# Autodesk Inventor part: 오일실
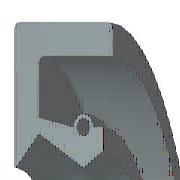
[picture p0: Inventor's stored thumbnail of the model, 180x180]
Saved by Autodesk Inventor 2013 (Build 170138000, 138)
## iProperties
IsCustomPart: 0
Created: 2014-10
Part Number: 오일실
Material: 고무
Description: 오일-실
Document SubType Name: Modeling
Standard: KS B 2804
Designer: KYOUNG IL JANG
Standards Organization: KS
Language: ko-KR
Size Designation: D - 17 32 8
Categories: <MemberInstance><Categories><Category DisplayName="샤프트 부품" InternalName="7f7aeb1f-a693-4053-b835-cee3144e0d98" Mnemonic="SHFT"><Category DisplayName="실링" Intern
Density: 0.93 g/cm^3
Mass: 2.28027 g
Surface Area: 32.1224 cm^2
Volume: 2.45191 cm^3
Author: SeoGD™ [www.esajin.kr]
Revision Number: 1
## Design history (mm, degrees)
revolve "본체" stored, may be unused: angle "d17" = 90 deg
revolve "스프링1" stored, may be unused: angle "d18" = 90 deg
body "Solid1"
sketch "스케치1"
  geometry: L1 (0, 16)-(8, 16); L2 (8, 14.25)-(1.75, 14.25); L3 (1.75, 10.25)-(4.9, 8.5); L4 (4.9, 8.5)-(0, 8.5); L5 (0, 0)-(9.586, 0) reference; L6 (4.9, 8.5)-(6.3, 9.375); L7 (0, 18)-(0, -3) reference; L8 (-1.941, 0)-(11.507, 0) reference; L9 (4.2, 10.6)-(1.75, 11.21); L10 (1.75, 11.21)-(1.75, 14.25); L11 (0, 16)-(0, 8.588); L12 (4.9, 8.5)-(0, 8.5); L13 (1.75, 10.25)-(0.152, 8.528); L14 (8, 16)-(8, 14.25); L15 (5.6, 10.6)-(6.3, 10.6); L16 (6.3, 10.6)-(6.3, 9.375); C1 r 0.455 at (4.9, 10.6); A1 r 0.7 centre (4.9, 10.6) between (5.6, 10.6) and (4.2, 10.6); A2 r 0.088 centre (0.088, 8.588) between (0, 8.588) and (0.152, 8.528); 1 further point
  constraints: 28 end point, 5 horizontal alignment, 5 point on line, 4 point on circle, 4 vertical alignment, 3 centre point, 3 tangent, 2 collinear, 2 horizontal, 2 perpendicular, 1 coincident, 1 parallel
  dimensions: "d0" = 32 diameter of L1 L5 (= SD2); "d1" = 1.75 distance of L1.end L2.start (= SD); "d2" = 0.91 diameter of C1 (= SPDI); "d3" = 1.4 diameter of A1 (= SPDA); "d4" = 17 diameter of L3.end L5 (= NND); "d5" = 20.5 diameter of L3.start L5 (= TKDM); "d7" = 22.42 diameter of L9.end L5 (= TKDM + 0.24 x SWDT); "d8" = 1.75 distance between parallel lines of L11 L10 (= SD); "d9" = 4.9 distance from line of L11 C1.centre (= SPDST); "d10" = 21.2 diameter of C1.centre L5 (= HLDM); "d11" = 0.0875 radius of A2 (= 0.25 x LAB); "d12" = 6.3 distance between parallel lines of L11 L16 (= SDI); "d13" = 18.75 diameter of L6.end L5 (= ABDM); "d14" = 8 distance from line of L11 L1.end (= SWDT)
fillet "모깎기1" dims "d6" = 0.3 (= RR)
other parameters: "SD2" = 32 [user parameter; used in 1 equation term], "SWDT" = 8 [user parameter; used in 2 equation terms], "RR" = 0.3 [user parameter; used in 1 equation term], "SD" = 1.75 [user parameter; used in 2 equation terms], "NND" = 17 [user parameter; used in 1 equation term], "SPDA" = 1.4 [user parameter; used in 1 equation term], "SPDI" = 0.91 [user parameter; used in 1 equation term], "TKDM" = 20.5 [user parameter; used in 2 equation terms], "HLDM" = 21.2 [user parameter; used in 1 equation term], "ABDM" = 18.75 [user parameter; used in 1 equation term], "SDI" = 6.3 [user parameter; used in 1 equation term], "SPDST" = 4.9 [user parameter; used in 1 equation term], "LAB" = 0.35 [user parameter; used in 1 equation term], "d15" = 0, "d16" = 0, "d19" = 0
